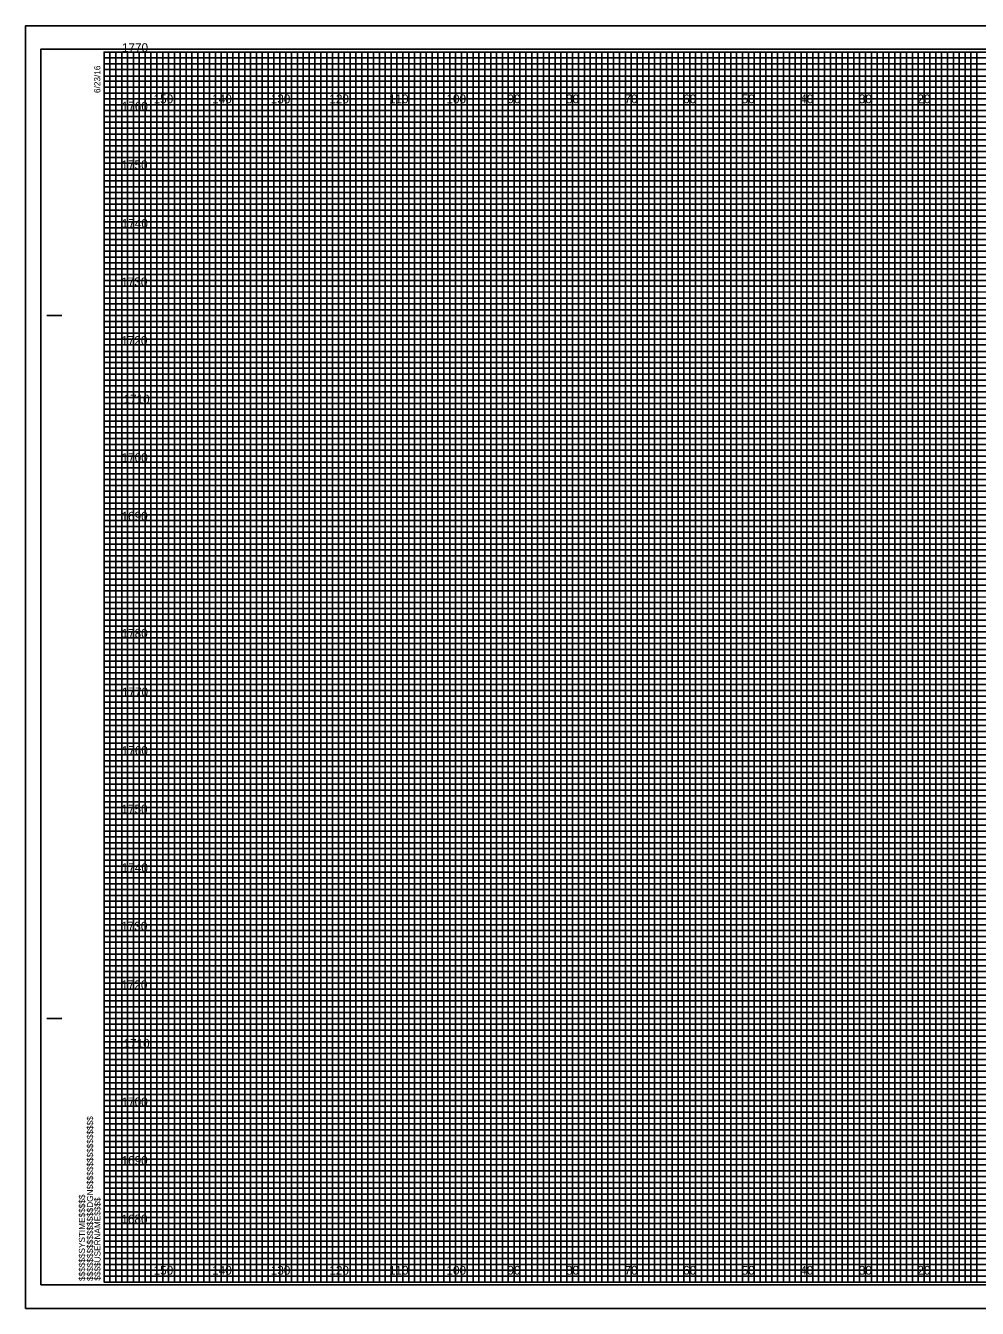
# Model space of a CAD drawing. Extents: x -419 to 4739, y -630 to 13534.
# Drawn here: x 4050.9 to 4213.4, y -25.4 to 193.6 of the extents above; entities that cross this region are included whole.
import ezdxf

# ---------------------------------------------------------------- set-up
doc = ezdxf.new("R2010")
doc.units = 0
for name, color, linetype in [('Old_Level_62', 7, 'Continuous'), ('Pattern 1', 7, 'Continuous'), ('Pattern 18', 7, 'Continuous'), ('Pattern 4', 7, 'Continuous'), ('Pattern 5', 7, 'Continuous'), ('Prop Dimension', 7, 'Continuous'), ('Prop Horizontal Alignment', 7, 'Continuous'), ('Raster_Level_0', 7, 'Continuous'), ('Scratch_Level_0', 7, 'Continuous'), ('Scratch_Level_3', 7, 'Continuous'), ('Scratch_Level_5', 7, 'Continuous')]:
    doc.layers.add(name, color=color, linetype=linetype)

msp = doc.modelspace()

# ---------------------------------------------------------------- linework, layer by layer
at = {"layer": 'Old_Level_62'}
for p, q in [((4054.48, 144.07), (4056.98, 144.07)), ((4054.58, 144.07), (4057.08, 144.07)), ((4054.48, 24.07), (4056.98, 24.07)), ((4054.58, 24.07), (4057.08, 24.07)), ((4064.28, -20.93), (4064.28, -20.93)), ((4064.28, -20.93), (4064.28, -20.93)), ((4064.28, -20.93), (4064.28, -20.93)), ((4064.28, -20.93), (4064.28, -20.93)), ((4064.28, -20.93), (4064.28, -20.93)), ((4064.28, -20.93), (4064.28, -20.93)), ((4064.28, -20.93), (4064.28, -20.93))]:
    msp.add_line(p, q, dxfattribs=at)
msp.add_lwpolyline([(4384.28, 189.07), (4064.28, 189.07), (4064.28, -20.93), (4384.28, -20.93)], close=True, dxfattribs=at)
at = {"layer": 'Pattern 18'}
msp.add_lwpolyline([(4050.88, -25.43), (4387.58, -25.43), (4387.58, 193.57), (4050.88, 193.57)], close=True, dxfattribs=at)
at = {"layer": 'Pattern 4'}
for p, q in [((4064.28, 188.07), (4324.28, 188.07)), ((4324.28, 187.05), (4064.28, 187.05)), ((4064.28, 187.05), (4064.28, 186.07)), ((4064.28, 186.07), (4324.28, 186.07)), ((4324.28, 184.96), (4064.28, 184.96)), ((4064.28, 184.96), (4064.28, 183.07)), ((4064.28, 183.07), (4384.28, 183.07))]:
    msp.add_line(p, q, dxfattribs=at)
for points in [[(4064.28, 182.07), (4334.28, 182.07), (4384.28, 182.07), (4384.28, 181.07), (4064.28, 181.07)], [(4064.28, 180.07), (4384.28, 180.07), (4384.28, 178.07), (4064.28, 178.07)], [(4064.28, 177.07), (4384.28, 177.07), (4384.28, 176.07), (4064.28, 176.05)], [(4064.28, 175.07), (4384.28, 175.07), (4384.28, 173.07), (4064.28, 173.07)], [(4064.28, 172.07), (4384.28, 172.07), (4384.28, 171.07), (4064.28, 171.07)], [(4064.28, 170.07), (4384.28, 170.07), (4384.28, 168.07), (4064.28, 168.07)], [(4064.28, 167.07), (4384.28, 167.07), (4384.28, 166.07), (4064.28, 166.07)], [(4064.28, 165.07), (4384.28, 165.07), (4384.28, 163.07), (4064.28, 163.07)], [(4064.28, 162.07), (4384.28, 162.07), (4384.28, 161.07), (4064.28, 161.07)], [(4064.28, 160.07), (4384.28, 160.07), (4384.28, 158.07), (4064.28, 158.07)], [(4064.28, 157.07), (4384.28, 157.07), (4384.28, 156.07), (4064.28, 156.07)], [(4064.28, 155.07), (4384.28, 155.07), (4384.28, 153.02), (4384.28, 152.07), (4384.28, 151.07), (4064.28, 151.07)], [(4064.28, 153.07), (4384.28, 153.07), (4384.28, 152.07), (4064.28, 152.07)], [(4064.28, 150.07), (4384.28, 150.07), (4384.28, 148.07), (4064.28, 148.1)], [(4064.28, 148.1), (4384.28, 148.07), (4384.28, 147.07), (4064.28, 147.07)], [(4064.28, 146.07), (4384.28, 146.07), (4384.28, 145.07), (4064.28, 145.07)], [(4064.28, 143.07), (4384.28, 143.07), (4384.28, 142.07), (4064.28, 142.07)], [(4064.28, 141.07), (4384.28, 141.07), (4384.28, 140.07), (4064.28, 140.07)], [(4064.21, 137.96), (4384.28, 137.96), (4384.28, 136.95), (4064.21, 136.95)], [(4064.28, 136.07), (4384.28, 136.07), (4384.28, 135.07), (4064.28, 135.07)], [(4064.28, 133.07), (4384.28, 133.07), (4384.28, 132.07), (4064.28, 132.07)], [(4064.28, 131.07), (4384.28, 131.07), (4384.28, 130.07), (4064.28, 130.07)], [(4064.28, 128.07), (4384.28, 128.07), (4384.28, 127.07), (4064.28, 127.07)], [(4064.28, 126.07), (4384.28, 126.07), (4384.28, 125.07), (4064.28, 125.07)], [(4064.28, 123.07), (4384.28, 123.07), (4384.28, 122.07), (4064.28, 122.07)], [(4064.28, 121.07), (4384.28, 121.07), (4384.28, 120.07), (4064.28, 120.07)], [(4064.28, 118.07), (4384.28, 118.07), (4384.27, 117.05), (4064.28, 117.07)], [(4064.28, 116.07), (4384.28, 116.07), (4384.28, 115.07), (4064.28, 115.07)], [(4064.28, 113.07), (4384.28, 113.07), (4384.28, 112.07), (4064.28, 112.07)], [(4064.28, 111.07), (4384.28, 111.07), (4384.28, 110.07), (4064.28, 110.07)], [(4064.28, 108.07), (4384.28, 108.07), (4384.28, 107.07), (4064.28, 107.07)], [(4064.28, 106.07), (4384.28, 106.07), (4384.28, 105.07), (4064.28, 105.07)], [(4064.28, 103.07), (4384.28, 103.07), (4384.28, 102.07), (4064.28, 102.07)], [(4064.28, 101.07), (4384.28, 101.07), (4384.28, 100.07), (4064.28, 100.07)], [(4064.28, 98.07), (4384.28, 98.07), (4384.28, 97.07), (4064.28, 97.07)], [(4064.28, 96.06), (4384.35, 95.98), (4384.28, 95.07), (4064.28, 95.07)], [(4064.28, 93.07), (4384.28, 93.07), (4384.28, 92.07), (4064.28, 92.07)], [(4064.28, 91.07), (4384.28, 91.07), (4384.28, 90.07), (4064.28, 90.07)], [(4064.28, 88.07), (4384.28, 88.07), (4384.28, 87.07), (4064.28, 87.07)], [(4064.28, 86.07), (4384.28, 86.07), (4384.28, 85.07), (4064.28, 85.07)], [(4064.28, 83.07), (4384.28, 83.07), (4384.28, 82.07), (4064.28, 82.07)], [(4064.28, 81.07), (4384.28, 81.07), (4384.28, 80.07), (4064.28, 80.07)], [(4064.28, 78.07), (4384.28, 78.07), (4384.28, 77.07), (4064.28, 77.07)], [(4064.28, 76.07), (4384.28, 76.07), (4384.28, 75.07), (4064.28, 75.07)], [(4064.28, 73.07), (4384.28, 73.07), (4384.28, 72.07), (4064.28, 72.07)], [(4064.28, 71.07), (4384.28, 71.07), (4384.28, 70.07), (4064.28, 70.07)], [(4064.28, 68.07), (4384.28, 68.07), (4384.28, 67.07), (4064.28, 67.07)], [(4064.28, 66.07), (4384.28, 66.07), (4384.28, 65.07), (4064.28, 65.07)], [(4064.28, 63.07), (4384.28, 63.07), (4384.28, 62.07), (4064.28, 62.07)], [(4064.28, 61.07), (4384.28, 61.07), (4384.28, 60.07), (4064.28, 60.07)], [(4064.28, 58.07), (4384.28, 58.07), (4384.27, 57.05), (4064.28, 57.07)], [(4064.28, 56.07), (4384.28, 56.07), (4384.28, 55.07), (4064.28, 55.07)], [(4064.28, 53.07), (4384.28, 53.07), (4384.28, 52.07), (4064.28, 52.07)], [(4064.28, 51.07), (4384.28, 51.07), (4384.28, 50.07), (4064.28, 50.07)], [(4064.28, 48.07), (4384.28, 48.07), (4384.28, 47.07), (4064.28, 47.07)], [(4064.28, 46.07), (4384.28, 46.07), (4384.28, 45.07), (4064.28, 45.07)], [(4064.28, 43.07), (4384.28, 43.07), (4384.28, 42.07), (4064.28, 42.07)], [(4064.28, 41.07), (4384.28, 41.07), (4384.28, 40.07), (4064.28, 40.07)], [(4064.28, 38.07), (4384.28, 38.07), (4384.28, 37.07), (4064.28, 37.07)], [(4064.28, 36.06), (4384.35, 35.98), (4384.28, 35.07), (4064.28, 35.07)], [(4064.28, 33.07), (4384.28, 33.07), (4384.28, 32.07), (4064.28, 32.07)], [(4064.28, 31.07), (4384.28, 31.07), (4384.28, 30.07), (4064.28, 30.07)], [(4064.28, 28.07), (4384.28, 28.07), (4384.28, 27.07), (4064.28, 27.07)], [(4064.28, 26.07), (4384.28, 26.07), (4384.28, 25.07), (4064.28, 25.07)], [(4064.28, 23.07), (4384.28, 23.07), (4384.28, 22.07), (4064.28, 22.07)], [(4064.28, 21.07), (4384.28, 21.07), (4384.28, 20.07), (4064.28, 20.07)], [(4064.28, 18.07), (4384.28, 18.07), (4384.28, 17.07), (4064.28, 17.07)], [(4064.28, 16.07), (4384.28, 16.07), (4384.28, 15.07), (4064.28, 15.07)], [(4064.28, 13.07), (4384.28, 13.07), (4384.28, 12.07), (4064.28, 12.07)], [(4064.28, 11.07), (4384.28, 11.07), (4384.28, 10.07), (4064.28, 10.07)], [(4064.28, 8.07), (4384.28, 8.07), (4384.28, 7.07), (4064.28, 7.07)], [(4064.28, 6.07), (4384.28, 6.07), (4384.28, 5.07), (4064.28, 5.07)], [(4064.28, 3.07), (4384.28, 3.07), (4384.28, 2.07), (4064.28, 2.07)], [(4064.28, 1.07), (4384.28, 1.07), (4384.28, 0.07), (4064.28, 0.07)], [(4064.28, -1.93), (4384.28, -1.93), (4384.28, -2.93), (4064.28, -2.93)], [(4064.28, -3.93), (4384.28, -3.93), (4384.28, -4.93), (4064.28, -4.93)], [(4064.28, -6.93), (4384.28, -6.93), (4384.28, -7.93), (4064.28, -7.93)], [(4064.28, -8.93), (4384.28, -8.93), (4384.28, -9.93), (4064.28, -9.93)], [(4064.28, -11.93), (4384.28, -11.93), (4384.28, -12.93), (4064.28, -12.93)], [(4064.28, -13.93), (4384.28, -13.93), (4384.28, -14.93), (4064.28, -14.93)], [(4064.28, -16.93), (4384.28, -16.93), (4384.28, -17.93), (4064.28, -17.93)], [(4064.28, -18.93), (4384.28, -18.93), (4384.28, -19.93), (4064.28, -19.93)]]:
    msp.add_lwpolyline(points, dxfattribs=at)
at = {"layer": 'Pattern 5'}
for p, q in [((4387.58, 193.57), (4050.88, 193.57)), ((4050.88, 193.57), (4050.88, -25.43)), ((4050.88, -25.43), (4387.58, -25.43))]:
    msp.add_line(p, q, dxfattribs=at)
at = {"layer": 'Prop Dimension'}
for points in [[(4064.28, -20.93), (4065.28, -20.93), (4065.28, 189.07), (4066.28, 189.07), (4066.28, -20.93)], [(4066.28, -20.93), (4067.28, -20.93), (4067.28, 189.07), (4068.28, 189.07), (4068.28, -20.93)], [(4069.28, -20.93), (4070.28, -20.93), (4070.28, 189.07), (4071.28, 189.07), (4071.28, -20.93)], [(4071.28, -20.93), (4072.28, -20.93), (4072.28, 189.07), (4073.28, 189.07), (4073.28, -20.93)], [(4074.28, -20.93), (4075.28, -20.93), (4075.28, 189.07), (4076.28, 189.07), (4076.28, -20.93)], [(4076.28, -20.93), (4077.28, -20.93), (4077.28, 189.07), (4078.28, 189.07), (4078.28, -20.93)], [(4079.28, -20.93), (4080.28, -20.93), (4080.28, 189.07), (4081.28, 189.07), (4081.28, -20.93)], [(4081.28, -20.93), (4082.28, -20.93), (4082.28, 189.07), (4083.28, 189.07), (4083.28, -20.93)], [(4084.28, -20.93), (4085.28, -20.93), (4085.28, 189.07), (4086.28, 189.07), (4086.28, -20.93)], [(4086.28, -20.93), (4087.28, -20.93), (4087.28, 189.07), (4088.28, 189.07), (4088.28, -20.93)], [(4089.28, -20.93), (4090.28, -20.93), (4090.28, 189.07), (4091.28, 189.07), (4091.28, -20.93)], [(4091.28, -20.93), (4092.28, -20.93), (4092.28, 189.07), (4093.28, 189.07), (4093.28, -20.93)], [(4094.28, -20.93), (4095.28, -20.93), (4095.28, 189.07), (4096.28, 189.07), (4096.28, -20.93)], [(4096.28, -20.93), (4097.28, -20.93), (4097.28, 189.07), (4098.28, 189.07), (4098.28, -20.93)], [(4099.28, -20.93), (4100.28, -20.93), (4100.28, 189.07), (4101.28, 189.07), (4101.28, -20.93)], [(4101.28, -20.93), (4102.28, -20.93), (4102.28, 189.07), (4103.28, 189.07), (4103.28, -20.93)], [(4104.28, -20.93), (4105.28, -20.93), (4105.28, 189.07), (4106.28, 189.07), (4106.28, -20.93)], [(4106.28, -20.93), (4107.28, -20.93), (4107.28, 189.07), (4108.28, 189.07), (4108.28, -20.93)], [(4109.28, -20.93), (4110.28, -20.93), (4110.28, 189.07), (4111.28, 189.07), (4111.28, -20.93)], [(4111.28, -20.93), (4112.28, -20.93), (4112.28, 189.07), (4113.28, 189.07), (4113.28, -20.93)], [(4114.28, -20.93), (4115.28, -20.93), (4115.28, 189.07), (4116.28, 189.07), (4116.28, -20.93)], [(4116.28, -20.93), (4117.28, -20.93), (4117.28, 189.07), (4118.28, 189.07), (4118.28, -20.93)], [(4119.28, -20.93), (4120.28, -20.93), (4120.28, 189.07), (4121.28, 189.07), (4121.28, -20.93)], [(4121.28, -20.93), (4122.28, -20.93), (4122.28, 189.07), (4123.28, 189.07), (4123.28, -20.93)], [(4124.28, -20.93), (4125.28, -20.93), (4125.28, 189.07), (4126.28, 189.07), (4126.28, -20.93)], [(4126.28, -20.93), (4127.28, -20.93), (4127.28, 189.07), (4128.28, 189.07), (4128.28, -20.93)], [(4129.28, -20.93), (4130.28, -20.93), (4130.28, 189.07), (4131.28, 189.07), (4131.28, -20.93)], [(4131.28, -20.93), (4132.28, -20.93), (4132.28, 189.07), (4133.28, 189.07), (4133.28, -20.93)], [(4134.28, -20.93), (4135.28, -20.93), (4135.28, 189.07), (4136.28, 189.07), (4136.28, -20.93)], [(4136.28, -20.93), (4137.28, -20.93), (4137.28, 189.07), (4138.28, 189.07), (4138.28, -20.93)], [(4139.28, -20.93), (4140.28, -20.93), (4140.28, 189.07), (4141.28, 189.07), (4141.28, -20.93)], [(4141.28, -20.93), (4142.28, -20.93), (4142.28, 189.07), (4143.28, 189.07), (4143.28, -20.93)], [(4144.28, -20.93), (4145.28, -20.93), (4145.28, 189.07), (4146.28, 189.07), (4146.28, -20.93)], [(4146.28, -20.93), (4147.28, -20.93), (4147.28, 189.07), (4148.28, 189.07), (4148.28, -20.93)], [(4149.28, -20.93), (4150.28, -20.93), (4150.28, 189.07), (4151.28, 189.07), (4151.28, -20.93)], [(4151.28, -20.93), (4152.28, -20.93), (4152.28, 189.07), (4153.28, 189.07), (4153.28, -20.93)], [(4154.28, -20.93), (4155.28, -20.93), (4155.28, 189.07), (4156.28, 189.07), (4156.28, -20.93)], [(4156.28, -20.93), (4157.28, -20.93), (4157.28, 189.07), (4158.28, 189.07), (4158.28, -20.93)], [(4159.28, -20.93), (4160.28, -20.93), (4160.28, 189.07), (4161.28, 189.07), (4161.28, -20.93)], [(4161.28, -20.93), (4162.28, -20.93), (4162.28, 189.07), (4163.28, 189.07), (4163.28, -20.93)], [(4164.28, -20.93), (4165.28, -20.93), (4165.28, 189.07), (4166.28, 189.07), (4166.28, -20.93)], [(4166.28, -20.93), (4167.28, -20.93), (4167.28, 189.07), (4168.28, 189.07), (4168.28, -20.93)], [(4169.28, -20.93), (4170.28, -20.93), (4170.28, 189.07), (4171.28, 189.07), (4171.28, -20.93)], [(4171.28, -20.93), (4172.28, -20.93), (4172.28, 189.07), (4173.28, 189.07), (4173.28, -20.93)], [(4174.28, -20.93), (4175.28, -20.93), (4175.28, 189.07), (4176.28, 189.07), (4176.28, -20.93)], [(4176.28, -20.93), (4177.28, -20.93), (4177.28, 189.07), (4178.28, 189.07), (4178.28, -20.93)], [(4179.28, -20.93), (4180.28, -20.93), (4180.28, 189.07), (4181.28, 189.07), (4181.28, -20.93)], [(4181.28, -20.93), (4182.28, -20.93), (4182.28, 189.07), (4183.28, 189.07), (4183.28, -20.93)], [(4184.28, -20.93), (4185.28, -20.93), (4185.28, 189.07), (4186.28, 189.07), (4186.28, -20.93)], [(4186.28, -20.93), (4187.28, -20.93), (4187.28, 189.07), (4188.28, 189.07), (4188.28, -20.93)], [(4189.28, -20.93), (4190.28, -20.93), (4190.28, 189.07), (4191.28, 189.07), (4191.28, -20.93)], [(4191.28, -20.93), (4192.28, -20.93), (4192.28, 189.07), (4193.28, 189.07), (4193.28, -20.93)], [(4194.28, -20.93), (4195.28, -20.93), (4195.28, 189.07), (4196.28, 189.07), (4196.28, -20.93)], [(4196.28, -20.93), (4197.28, -20.93), (4197.28, 189.07), (4198.28, 189.07), (4198.28, -20.93)], [(4199.28, -20.93), (4200.28, -20.93), (4200.28, 189.07), (4201.28, 189.07), (4201.28, -20.93)], [(4201.28, -20.93), (4202.28, -20.93), (4202.28, 189.07), (4203.28, 189.07), (4203.28, -20.93)], [(4204.28, -20.93), (4205.28, -20.93), (4205.28, 189.07), (4206.28, 189.07), (4206.28, -20.93)], [(4206.28, -20.93), (4207.28, -20.93), (4207.28, 189.07), (4208.28, 189.07), (4208.28, -20.93)], [(4209.28, -20.93), (4210.28, -20.93), (4210.28, 189.07), (4211.28, 189.07), (4211.28, -20.93)], [(4211.28, -20.93), (4212.28, -20.93), (4212.28, 189.07), (4213.28, 189.07), (4213.28, -20.93)]]:
    msp.add_lwpolyline(points, dxfattribs=at)
at = {"layer": 'Prop Horizontal Alignment'}
for points in [[(4064.28, 189.07), (4069.28, 189.07), (4069.28, -20.93), (4079.28, -20.93), (4079.28, 189.07), (4089.28, 189.07), (4089.28, -20.93), (4099.28, -20.93), (4099.28, 189.07), (4109.28, 189.07), (4109.28, -20.93), (4119.28, -20.93), (4119.28, 189.07), (4129.28, 189.07), (4129.28, -20.93), (4139.28, -20.93), (4139.28, 189.07), (4149.28, 189.07), (4149.28, -20.93), (4159.28, -20.93), (4159.28, 189.07), (4169.28, 189.07), (4169.28, -20.93), (4179.28, -20.93), (4179.28, 189.07), (4189.28, 189.07), (4189.28, -20.93), (4199.28, -20.93), (4199.28, 189.07), (4209.28, 189.07), (4209.28, -20.93), (4219.28, -20.93)], [(4064.28, 184.07), (4339.28, 184.07)], [(4064.28, 164.07), (4384.28, 164.07), (4384.28, 174.07), (4064.28, 174.07)], [(4064.28, 144.07), (4384.28, 144.07), (4384.28, 154.07), (4064.28, 154.07)], [(4064.28, 124.07), (4384.28, 124.07), (4384.28, 134.07), (4064.28, 134.07)], [(4064.28, 104.07), (4384.28, 104.07), (4384.28, 114.07), (4064.28, 114.07)], [(4064.28, 84.07), (4384.28, 84.07), (4384.28, 94.07), (4064.28, 94.07)], [(4064.28, 64.07), (4384.28, 64.07), (4384.28, 74.07), (4064.28, 74.07)], [(4064.28, 44.07), (4384.28, 44.07), (4384.28, 54.07), (4064.28, 54.07)], [(4064.28, 24.07), (4384.28, 24.07), (4384.28, 34.07), (4064.28, 34.07)], [(4064.28, 4.07), (4384.28, 4.07), (4384.28, 14.07), (4064.28, 14.07)], [(4064.28, -15.93), (4384.28, -15.93), (4384.28, -5.93), (4064.28, -5.93)]]:
    msp.add_lwpolyline(points, dxfattribs=at)
at = {"layer": 'Scratch_Level_0'}
for p, q in [((4074.28, -20.93), (4074.28, 189.07)), ((4084.28, -20.93), (4084.28, 189.07)), ((4094.28, -20.93), (4094.28, 189.07)), ((4104.28, -20.93), (4104.28, 189.07)), ((4114.28, -20.93), (4114.28, 189.07)), ((4124.28, -20.93), (4124.28, 189.07)), ((4134.28, -20.93), (4134.28, 189.07)), ((4144.28, -20.93), (4144.28, 189.07)), ((4154.28, -20.93), (4154.28, 189.07)), ((4164.28, -20.93), (4164.28, 189.07)), ((4174.28, -20.93), (4174.28, 189.07)), ((4184.28, -20.93), (4184.28, 189.07)), ((4194.28, -20.93), (4194.28, 189.07)), ((4204.28, -20.93), (4204.28, 189.07)), ((4064.28, 179.07), (4384.28, 179.07)), ((4064.28, 169.07), (4384.28, 169.07)), ((4064.28, 159.07), (4384.28, 159.07)), ((4064.28, 149.07), (4384.28, 149.07)), ((4064.28, 139.07), (4384.28, 139.07)), ((4064.28, 129.07), (4384.28, 129.07)), ((4064.28, 119.07), (4384.28, 119.07)), ((4064.28, 109.07), (4384.28, 109.07)), ((4064.28, 99.07), (4384.28, 99.07)), ((4064.28, 89.07), (4384.28, 89.07)), ((4064.28, 79.07), (4384.28, 79.07)), ((4064.28, 69.07), (4384.28, 69.07)), ((4064.28, 59.07), (4384.28, 59.07)), ((4064.28, 49.07), (4384.28, 49.07)), ((4064.28, 39.07), (4384.28, 39.07)), ((4064.28, 29.07), (4384.28, 29.07)), ((4064.28, 19.07), (4384.28, 19.07)), ((4064.28, 9.07), (4384.28, 9.07)), ((4064.28, -0.93), (4384.28, -0.93)), ((4064.28, -10.93), (4384.28, -10.93))]:
    msp.add_line(p, q, dxfattribs=at)
at = {"layer": 'Scratch_Level_3'}
for p, q in [((4074.28, 189.07), (4064.28, 189.07)), ((4074.28, -20.93), (4074.28, 189.07)), ((4094.28, 189.07), (4084.28, 189.07)), ((4084.28, 189.07), (4084.28, -20.93)), ((4094.28, -20.93), (4094.28, 189.07)), ((4114.28, 189.07), (4104.28, 189.07)), ((4104.28, 189.07), (4104.28, -20.93)), ((4114.28, -20.93), (4114.28, 189.07)), ((4134.28, 189.07), (4124.28, 189.07)), ((4124.28, 189.07), (4124.28, -20.93)), ((4134.28, -20.93), (4134.28, 189.07)), ((4154.28, 189.07), (4144.28, 189.07)), ((4144.28, 189.07), (4144.28, -20.93)), ((4154.28, -20.93), (4154.28, 189.07)), ((4174.28, 189.07), (4164.28, 189.07)), ((4164.28, 189.07), (4164.28, -20.93)), ((4174.28, -20.93), (4174.28, 189.07)), ((4194.28, 189.07), (4184.28, 189.07)), ((4184.28, 189.07), (4184.28, -20.93)), ((4194.28, -20.93), (4194.28, 189.07)), ((4214.28, 189.07), (4204.28, 189.07)), ((4204.28, 189.07), (4204.28, -20.93)), ((4084.28, -20.93), (4074.28, -20.93)), ((4104.28, -20.93), (4094.28, -20.93)), ((4124.28, -20.93), (4114.28, -20.93)), ((4144.28, -20.93), (4134.28, -20.93)), ((4164.28, -20.93), (4154.28, -20.93)), ((4184.28, -20.93), (4174.28, -20.93)), ((4204.28, -20.93), (4194.28, -20.93))]:
    msp.add_line(p, q, dxfattribs=at)
for points in [[(4064.28, 179.07), (4384.28, 179.07), (4384.28, 169.07), (4064.28, 169.07)], [(4064.28, 159.07), (4384.28, 159.07), (4384.28, 149.07), (4064.28, 149.07)], [(4064.28, 139.07), (4384.28, 139.07), (4384.28, 129.07), (4064.28, 129.07)], [(4064.28, 119.07), (4384.28, 119.07), (4384.28, 109.07), (4064.28, 109.07)], [(4064.28, 99.07), (4384.28, 99.07), (4384.28, 89.07), (4064.28, 89.07)], [(4064.28, 79.07), (4384.28, 79.07), (4384.28, 69.07), (4064.28, 69.07)], [(4064.28, 59.07), (4384.28, 59.07), (4384.28, 49.07), (4064.28, 49.07)], [(4064.28, 39.07), (4384.28, 39.07), (4384.28, 29.07), (4064.28, 29.07)], [(4064.28, 19.07), (4384.28, 19.07), (4384.28, 9.07), (4064.28, 9.07)], [(4064.28, -0.93), (4384.28, -0.93), (4384.28, -10.93), (4064.28, -10.93)]]:
    msp.add_lwpolyline(points, dxfattribs=at)
at = {"layer": 'Scratch_Level_5'}
msp.add_lwpolyline([(4053.48, -21.43), (4386.68, -21.43), (4386.68, 189.57), (4053.48, 189.57)], close=True, dxfattribs=at)

# ---------------------------------------------------------------- texts
at = {"layer": 'Old_Level_62'}
for s, p in [('6/23/16', (4063.63, 182.07)), ('$$$$$$$$$$$$$$$$DGN$$$$$$$$$$$$$$$$', (4062.4, -20.75)), ('$$$$$$SYSTIME$$$$$', (4061.02, -20.75)), ('$$$$USERNAME$$$$', (4063.66, -20.7))]:
    msp.add_text(s, height=1.05, rotation=90, dxfattribs=at).set_placement(p)
at = {"layer": 'Pattern 1'}
for s, p in [('1770', (4067.32, 189.07)), ('1760', (4067.29, 179.07)), ('1750', (4067.24, 169.07)), ('1740', (4067.29, 159.07)), ('1730', (4067.2, 149.07)), ('1720', (4067.21, 139.07)), ('1710', (4067.59, 129.07)), ('1700', (4067.26, 119.07)), ('1690', (4067.25, 109.07)), ('1780', (4067.26, 89.07)), ('1770', (4067.32, 79.07)), ('1760', (4067.29, 69.07)), ('1750', (4067.24, 59.07)), ('1740', (4067.29, 49.07)), ('1730', (4067.2, 39.07)), ('1720', (4067.21, 29.07)), ('1710', (4067.59, 19.07)), ('1700', (4067.26, 9.07)), ('1690', (4067.25, -0.93)), ('1680', (4067.23, -10.93))]:
    msp.add_text(s, height=1.5, dxfattribs=at).set_placement(p)
at = {"layer": 'Raster_Level_0'}
for s, p in [('150', (4072.73, 180.32)), ('140', (4082.73, 180.32)), ('130', (4092.73, 180.32)), ('120', (4102.73, 180.32)), ('110', (4112.91, 180.32)), ('100', (4122.73, 180.32)), ('90', (4133.14, 180.32)), ('80', (4143.14, 180.32)), ('70', (4153.14, 180.32)), ('60', (4163.14, 180.32)), ('50', (4173.14, 180.32)), ('40', (4183.14, 180.32)), ('30', (4193.14, 180.32)), ('20', (4203.14, 180.32)), ('150', (4072.73, -19.68)), ('140', (4082.73, -19.68)), ('130', (4092.73, -19.68)), ('120', (4102.73, -19.68)), ('110', (4112.91, -19.68)), ('100', (4122.73, -19.68)), ('90', (4133.14, -19.68)), ('80', (4143.14, -19.68)), ('70', (4153.14, -19.68)), ('60', (4163.14, -19.68)), ('50', (4173.14, -19.68)), ('40', (4183.14, -19.68)), ('30', (4193.14, -19.68)), ('20', (4203.14, -19.68))]:
    msp.add_text(s, height=1.5, dxfattribs=at).set_placement(p)

doc.saveas('drawing.dxf')
